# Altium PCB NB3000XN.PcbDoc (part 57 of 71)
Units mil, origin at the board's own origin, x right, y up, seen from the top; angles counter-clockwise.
Board outline 9527.56 x 6929.77 mil, 6 copper layers (Top Layer, GND+SHIELD, MidLayer1, MidLayer2, P2 - 3V3+5V0, Bottom Layer), stack 62.375 mil thick; 832 components, 1027 nets, 4655 pads, 4981 vias.
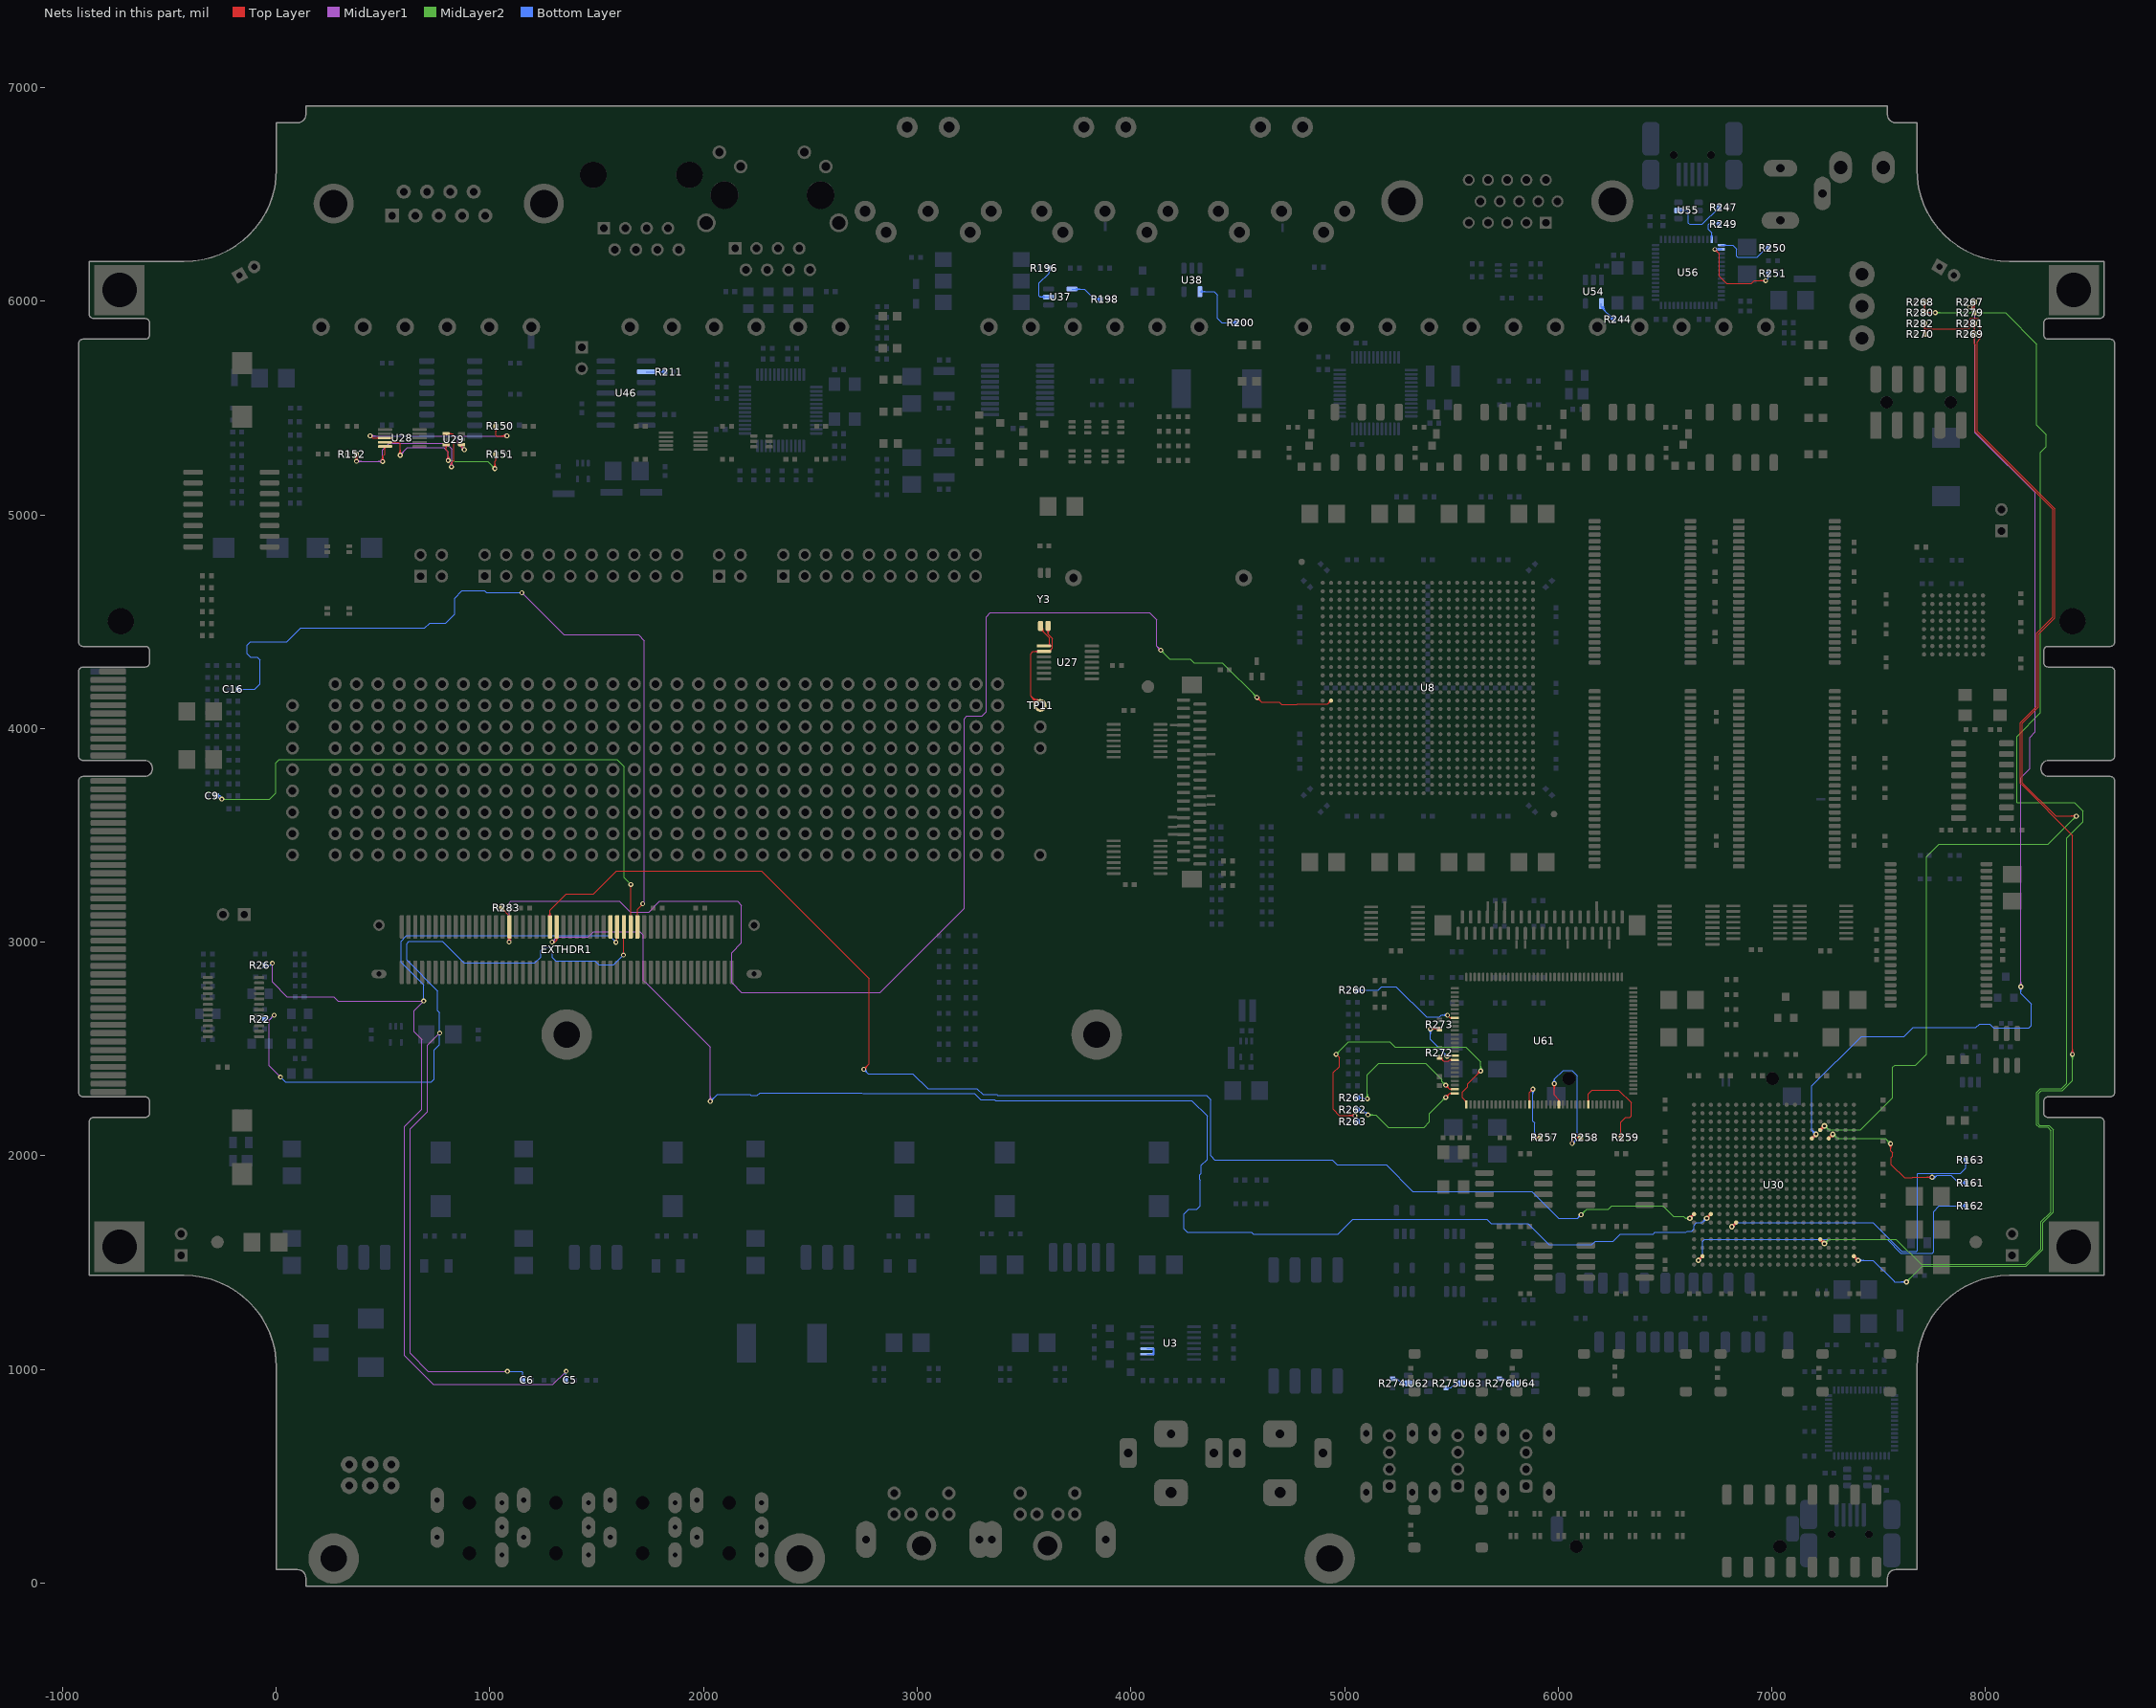
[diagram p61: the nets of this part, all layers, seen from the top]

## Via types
v1: diameter 23, hole 11.81, Top Layer to Bottom Layer, 3672 vias
v2: diameter 26, hole 11.81, Top Layer to Bottom Layer, 461 vias
v3: diameter 19, hole 11.81, Top Layer to Bottom Layer, tented both sides, 396 vias
v4: diameter 23.62, hole 11.81, Top Layer to Bottom Layer, 288 vias
v5: diameter 20, hole 11.81, Top Layer to Bottom Layer, 91 vias
v6: diameter 23, hole 11.81, Top Layer to Bottom Layer, tented both sides, 50 vias
v7: diameter 31, hole 11.81, Top Layer to Bottom Layer, 15 vias
v8: diameter 27.56, hole 11.81, Top Layer to Bottom Layer, tented both sides, 4 vias
v9: diameter 29, hole 11.81, Top Layer to Bottom Layer, 3 vias
v10: diameter 21, hole 11.81, Top Layer to Bottom Layer, 1 vias

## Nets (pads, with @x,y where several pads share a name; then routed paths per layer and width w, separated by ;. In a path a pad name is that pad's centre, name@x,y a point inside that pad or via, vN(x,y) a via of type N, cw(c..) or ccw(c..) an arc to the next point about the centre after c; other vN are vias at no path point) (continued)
NetR150_2: R150.2 U28.3 U29.4 | length 1239.4
  Top Layer w4: v4(440,5370) 450,5360 U28.3@509.29,5360 ; U28.3@479,5357.17 ccw(c472.17,5350.34) 472.17,5360 ccw(c472.17,5369.66) U28.3@479,5362.83 ; U29.4@864.34,5324.1 cw(c859.21,5317.17) 867.83,5317.17 ; U29.4@867.83,5328.82 867.83,5317.17 ; U29.4@871.33,5324.1 ccw(c876.46,5317.17) 867.83,5317.17 ; v4(880,5305) 867.83,5317.17 ; R150.2@1021.05,5407.92 cw(c1005.14,5392.01) 1027.64,5392.01 cw(c1050.14,5392.01) R150.2@1034.23,5407.92 ; R150.2@1023.88,5410.75 cw(c1014.8,5401.67) 1027.64,5401.67 cw(c1040.48,5401.67) R150.2@1031.4,5410.75 ; R150.2@1027.64,5415 1027.64,5372.36 1030,5370 v4(1080,5370) ; v4@1073.06,5363.06 ccw(c1056.31,5346.31) 1056.31,5370 ccw(c1056.31,5393.69) v4@1073.06,5376.94 ; v4@1075.89,5365.89 ccw(c1065.97,5355.97) 1065.97,5370 ccw(c1065.97,5384.03) v4@1075.89,5374.11
  MidLayer1 w4: v4(440,5370) 850,5370 ; v4@444.11,5365.89 cw(c454.03,5355.97) 454.03,5370 cw(c454.03,5384.03) v4@444.11,5374.11 ; v4@446.94,5363.06 cw(c463.69,5346.31) 463.69,5370 cw(c463.69,5393.69) v4@446.94,5376.94 ; v4@870.19,5305 ccw(c846.5,5305) 863.25,5321.75 ccw(c880,5338.5) v4@880,5314.81 ; v4@874.19,5305 ccw(c860.16,5305) 870.08,5314.92 ccw(c880,5324.84) v4@880,5310.81 ; v4(880,5305) 850,5335 850,5370 ; v4@1073.06,5363.06 ccw(c1056.31,5346.31) 1056.31,5370 ccw(c1056.31,5393.69) v4@1073.06,5376.94 ; v4@1075.89,5365.89 ccw(c1065.97,5355.97) 1065.97,5370 ccw(c1065.97,5384.03) v4@1075.89,5374.11 ; v4(1080,5370) 850,5370
NetR151_2: R151.2 U28.4 U29.3 | length 1293.9
  Top Layer w4: U28.4@509.29,5340.31 574.69,5340.31 580,5335 v4(580,5280) ; U28.4@539.58,5337.49 cw(c546.41,5330.66) 546.41,5340.31 cw(c546.41,5349.97) U28.4@539.58,5343.14 ; v4@573.06,5286.94 ccw(c556.31,5303.69) 580,5303.69 ccw(c603.69,5303.69) v4@586.94,5286.94 ; v4@575.89,5284.11 ccw(c565.97,5294.03) 580,5294.03 ccw(c594.03,5294.03) v4@584.11,5284.11 ; U29.3@790.85,5324.67 cw(c780.82,5314.64) 795,5314.64 cw(c809.18,5314.64) U29.3@799.15,5324.67 ; U29.3@795,5328.82 795,5305 805,5295 v1(805,5255) ; v1@798.28,5261.72 ccw(c782.06,5277.93) 805,5277.93 ccw(c827.93,5277.93) v1@811.72,5261.72 ; v1@801.11,5258.89 ccw(c791.72,5268.28) 805,5268.28 ccw(c818.28,5268.28) v1@808.89,5258.89 ; v1@1016.81,5223.43 ccw(c1000.59,5239.64) 1023.52,5239.64 ccw(c1046.46,5239.64) v1@1030.24,5223.43 ; v1@1019.64,5220.6 ccw(c1010.25,5229.99) 1023.52,5229.99 ccw(c1036.8,5229.99) v1@1027.41,5220.6 ; R151.2@1021.05,5277.92 cw(c1005.14,5262.01) 1027.64,5262.01 cw(c1050.13,5262.01) R151.2@1034.23,5277.92 ; v1(1023.52,5216.71) 1023.52,5250.89 1027.64,5255 R151.2@1027.64,5285 ; R151.2@1023.88,5280.75 cw(c1014.8,5271.67) 1027.64,5271.67 cw(c1040.48,5271.67) R151.2@1031.4,5280.75
  MidLayer1 w4: v4(580,5280) 615,5315 785,5315 805,5295 v1(805,5255) ; v4@580,5285.81 ccw(c580,5299.84) 589.92,5289.92 ccw(c599.84,5280) v4@585.81,5280 ; v4@580,5289.81 ccw(c580,5313.5) 596.75,5296.75 ccw(c613.5,5280) v4@589.81,5280 ; v1@798.28,5261.72 ccw(c782.06,5277.93) 805,5277.93 ccw(c827.93,5277.93) v1@811.72,5261.72 ; v1@801.11,5258.89 ccw(c791.72,5268.28) 805,5268.28 ccw(c818.28,5268.28) v1@808.89,5258.89
  MidLayer2 w4: v1(805,5255) 830,5255 835,5250 990.23,5250 v1(1023.52,5216.71) ; v1@808.89,5251.11 cw(c818.28,5241.72) 818.28,5255 cw(c818.28,5268.28) v1@808.89,5258.89 ; v1@811.72,5248.28 cw(c827.93,5232.06) 827.93,5255 cw(c827.93,5277.93) v1@811.72,5261.72 ; v1@1014.02,5216.71 ccw(c991.09,5216.71) 1007.31,5232.93 ccw(c1023.52,5249.14) v1@1023.52,5226.21 ; v1@1018.02,5216.71 ccw(c1004.75,5216.71) 1014.14,5226.1 ccw(c1023.52,5235.49) v1@1023.52,5222.21
NetR152_2: R152.2 U28.5 U29.1 | length 1361.7
  Top Layer w4: v1@368.65,5257.59 ccw(c352.43,5273.81) 375.37,5273.81 ccw(c398.3,5273.81) v1@382.08,5257.59 ; R152.2@369.59,5277.92 cw(c355.65,5263.97) 375.37,5263.97 ; v1@371.48,5254.76 ccw(c362.09,5264.15) 375.37,5264.15 ccw(c388.65,5264.15) v1@379.26,5254.76 ; v1(375.37,5250.87) 375.37,5284.19 R152.2@376.18,5285 ; v1@375.37,5260.05 cw(c400.64,5260.05) R152.2@382.77,5277.92 ; 375.37,5269.7 cw(c390.99,5269.7) R152.2@379.94,5280.75 ; v1@491.47,5256.76 ccw(c475.26,5272.98) 498.19,5272.98 ccw(c521.13,5272.98) v1@504.91,5256.76 ; v1@494.3,5253.93 ccw(c484.91,5263.32) 498.19,5263.32 ccw(c511.47,5263.32) v1@502.08,5253.93 ; v1(498.19,5250.04) 498.19,5273.9 509.29,5285 U28.5@509.29,5320.63 ; U28.5@506.46,5317.8 cw(c499.63,5310.97) 509.29,5310.97 cw(c518.95,5310.97) U28.5@512.12,5317.8 ; U29.1@795,5380 823.86,5380 831.86,5372 831.86,5255 820,5243.14 ; U29.1@808.01,5375.85 cw(c818.04,5365.82) 818.04,5380 cw(c818.04,5394.18) U29.1@808.01,5384.15 ; v4@814.63,5233.21 ccw(c808.13,5243.14) 820,5243.14 ; v4(820,5225) 820,5243.14 ; v4@825.37,5233.21 cw(c831.87,5243.14) 820,5243.14
  MidLayer1 w4: v1@373.52,5252.72 v1(375.37,5250.87) 444.11,5250.87 445.44,5249.54 498.19,5249.54 v1(498.19,5250.04) 498.19,5303.19 530,5335 795,5335 822.5,5307.5 822.5,5227.5 v4(820,5225) ; v1@379.26,5246.99 cw(c388.65,5237.6) 388.65,5250.87 cw(c388.65,5264.15) v1@379.26,5254.76 ; v1@382.08,5244.16 cw(c398.3,5227.94) 398.3,5250.87 cw(c398.3,5273.81) v1@382.08,5257.59 ; 474.05,5249.54 ccw(c474.05,5274.18) 491.47,5256.76 ccw(c475.26,5272.98) 498.19,5272.98 ccw(c521.13,5272.98) v1@504.91,5256.76 ; 476.46,5249.54 cw(c476.46,5228.31) v1@491.47,5243.32 ; 483.7,5249.54 ccw(c483.7,5264.53) 494.3,5253.93 ccw(c484.91,5263.32) 498.19,5263.32 ccw(c511.47,5263.32) v1@502.08,5253.93 ; 486.12,5249.54 cw(c486.12,5237.97) v1@494.3,5246.15 ; v4@813.06,5231.94 ccw(c790.28,5254.72) 822.5,5254.72 ; v4@815.89,5229.11 ccw(c799.94,5245.06) 822.5,5245.06 ; 822.5,5242.65 ccw(c837.65,5242.65) v4@826.94,5231.94
NetR161_2: R161.2 U30.D5 | length 1265.7
  Top Layer w4: v1@7548.81,2050.32 cw(c7532.59,2034.11) 7555.52,2034.11 cw(c7578.46,2034.11) v1@7562.24,2050.32 ; v1@7551.64,2053.15 cw(c7542.25,2043.76) 7555.52,2043.76 cw(c7568.8,2043.76) v1@7559.41,2053.15 ; v1(7555.52,2057.04) 7555.52,2023.76 7565.51,2013.78 7565.51,1999.02 7559.5,1993.02 7559.5,1959.44 7621.7,1897.24 7657.24,1897.24 7660,1900 v1(7750,1900) ; v1@7743.28,1893.28 ccw(c7727.06,1877.06) 7727.06,1900 ccw(c7727.06,1922.93) v1@7743.28,1906.72 ; v1@7746.11,1896.11 ccw(c7736.72,1886.72) 7736.72,1900 ccw(c7736.72,1913.28) v1@7746.11,1903.89
  Top Layer w8: U30.D5@7265.91,2081.54 v2(7285.59,2101.22) ; U30.D5@7265.91,2087.38 ccw(c7265.91,2101.48) 7275.88,2091.51 ccw(c7285.85,2081.54) U30.D5@7271.75,2081.54 ; v2@7276.59,2101.22 cw(c7254.86,2101.22) 7270.23,2085.86 cw(c7285.59,2070.49) v2@7285.59,2092.22
  MidLayer2 w4: v2@7285.59,2090.22 cw(c7285.59,2063.66) 7304.37,2082.44 cw(c7323.15,2101.22) v2@7296.59,2101.22 ; v2@7285.59,2094.22 cw(c7285.59,2077.32) 7297.54,2089.27 cw(c7309.49,2101.22) v2@7292.59,2101.22 ; v2(7285.59,2101.22) 7304.77,2082.04 7530.52,2082.04 v1(7555.52,2057.04) ; v1@7546.02,2057.04 ccw(c7523.09,2057.04) 7539.31,2073.26 ccw(c7555.52,2089.48) v1@7555.52,2066.54 ; v1@7550.02,2057.04 ccw(c7536.75,2057.04) 7546.14,2066.43 ccw(c7555.52,2075.82) v1@7555.52,2062.54
  Bottom Layer w4: v1@7745.93,1894.93 ccw(c7752.96,1903.69) 7760.9,1895.75 ; v1@7748.44,1898.05 ccw(c7755.77,1907.19) 7764.05,1898.91 ; v1@7750,1891.71 7756.86,1891.71 7757.57,1892.43 7773.52,1908.37 ; v1@7750,1892.18 v1(7750,1900) ; v1@7750.94,1901.17 ccw(c7758.58,1910.7) 7767.21,1902.06 ; v1@7753.44,1904.29 ccw(c7761.39,1914.2) 7770.37,1905.22 ; v1@7755.94,1907.41 ccw(c7764.2,1917.7) 7773.52,1908.37 ; R161.2@7902.23,1866.74 ccw(c7886.32,1850.84) 7886.32,1873.33 ccw(c7886.32,1895.83) R161.2@7902.23,1879.92 ; R161.2@7905.06,1869.57 ccw(c7895.98,1860.49) 7895.98,1873.33 ccw(c7895.98,1886.18) R161.2@7905.06,1877.09 ; R161.2@7908.82,1873.33 7873.52,1873.33 7838.48,1908.37 7773.52,1908.37
NetR162_2: R162.2 U30.W19 | length 1818.5
  Top Layer w8: v2(6655.67,1510.67) U30.W19@6675.35,1530.35 ; v2@6655.67,1519.67 ccw(c6655.67,1541.4) 6671.03,1526.03 ccw(c6686.4,1510.67) v2@6664.67,1510.67 ; U30.W19@6669.51,1530.35 cw(c6655.41,1530.35) 6665.38,1520.38 cw(c6675.35,1510.41) U30.W19@6675.35,1524.51
  Bottom Layer w4: v2(6655.67,1510.67) 6675.86,1530.86 6675.86,1600.04 6684.86,1609.04 7540,1609.04 7604.04,1545 7750,1545 7756.86,1551.86 7756.86,1640 ; v2@6655.67,1517.67 ccw(c6655.67,1534.57) 6667.62,1522.62 ccw(c6679.57,1510.67) v2@6662.67,1510.67 ; v2@6655.67,1521.67 ccw(c6655.67,1548.23) 6674.45,1529.45 ccw(c6693.23,1510.67) v2@6666.67,1510.67 ; 7756.86,1591.71 7756.86,1640 ; R162.2@7902.23,1758.41 ccw(c7886.32,1742.5) 7886.32,1765 ccw(c7886.32,1787.5) R162.2@7902.23,1771.59 ; R162.2@7905.06,1761.24 ccw(c7895.98,1752.16) 7895.98,1765 ccw(c7895.98,1777.84) R162.2@7905.06,1768.76 ; R162.2@7908.82,1765 7781.86,1765 7756.86,1740 7756.86,1640
NetR163_2: R163.2 U30.R15 | length 1799.5
  Top Layer w8: v2(6813.15,1668.15) U30.R15@6832.83,1687.83 ; v2@6813.15,1677.15 ccw(c6813.15,1698.88) 6828.51,1683.51 ccw(c6843.88,1668.15) v2@6822.15,1668.15 ; U30.R15@6826.99,1687.83 cw(c6812.89,1687.83) 6822.86,1677.86 cw(c6832.83,1667.89) U30.R15@6832.83,1681.99
  Bottom Layer w4: v2(6813.15,1668.15) 6832.71,1687.71 7472.65,1687.71 7607.35,1553 7678,1553 7681.86,1556.86 7681.86,1610 ; v2@6813.15,1675.15 ccw(c6813.15,1692.05) 6825.1,1680.1 ; v2@6813.15,1679.15 ccw(c6813.15,1705.71) 6831.93,1686.93 ccw(c6850.7,1668.15) v2@6824.15,1668.15 ; v2@6820.15,1668.15 cw(c6837.05,1668.15) 6825.1,1680.1 ; 7681.86,1588.71 7681.86,1610 ; R163.2@7902.23,1974.59 cw(c7886.32,1958.68) 7908.82,1958.68 cw(c7931.32,1958.68) R163.2@7915.41,1974.59 ; R163.2@7905.06,1977.41 cw(c7895.98,1968.33) 7908.82,1968.33 cw(c7921.66,1968.33) R163.2@7912.58,1977.41 ; R163.2@7908.82,1981.67 7908.82,1943.37 7883.44,1918 7683.15,1918 7681.86,1916.71 7681.86,1610
NetR196_1: R196.1 U37.2 | length 310.8
  Bottom Layer w4: U37.2@3594.16,6013.06 ccw(c3577.42,5996.31) 3577.42,6020 ccw(c3577.42,6043.69) U37.2@3594.16,6026.94 ; U37.2@3596.99,6015.89 ccw(c3587.07,6005.97) 3587.07,6020 ccw(c3587.07,6034.03) U37.2@3596.99,6024.11 ; R196.1@3609.59,6147.92 cw(c3593.68,6132.01) 3616.18,6132.01 cw(c3638.68,6132.01) R196.1@3622.77,6147.92 ; R196.1@3612.42,6150.75 cw(c3603.34,6141.67) 3616.18,6141.67 cw(c3629.02,6141.67) R196.1@3619.94,6150.75 ; U37.2@3614.88,6020 3575,6020 3570,6025 3570,6085 3616.18,6131.18 R196.1@3616.18,6155
NetR198_1: R198.1 U37.4 | length 268.1
  Bottom Layer w4: U37.4@3725.12,6057.4 3782.83,6057.4 3830.23,6010 R198.1@3858.82,6010 ; U37.4@3743.01,6053.29 cw(c3752.93,6043.37) 3752.93,6057.4 cw(c3752.93,6071.43) U37.4@3743.01,6061.51 ; U37.4@3745.84,6050.46 cw(c3762.58,6033.72) 3762.58,6057.4 cw(c3762.58,6081.09) U37.4@3745.84,6064.34 ; R198.1@3852.23,6003.41 ccw(c3836.32,5987.5) 3836.32,6010 ccw(c3836.32,6032.5) R198.1@3852.23,6016.59 ; R198.1@3855.06,6006.24 ccw(c3845.98,5997.16) 3845.98,6010 ccw(c3845.98,6022.84) R198.1@3855.06,6013.76
NetR200_1: R200.1 U38.4 | length 409.7
  Bottom Layer w4: U38.4@4323.24,6044.88 4390,6044.88 4405,6029.88 4405,5920 4425,5900 R200.1@4493.82,5900 ; U38.4@4327.35,6040.77 cw(c4337.27,6030.85) 4337.27,6044.88 cw(c4337.27,6058.91) U38.4@4327.35,6048.99 ; U38.4@4330.18,6037.94 cw(c4346.93,6021.2) 4346.93,6044.88 cw(c4346.93,6068.57) U38.4@4330.18,6051.82 ; R200.1@4487.23,5893.41 ccw(c4471.32,5877.5) 4471.32,5900 ccw(c4471.32,5922.5) R200.1@4487.23,5906.59 ; R200.1@4490.06,5896.24 ccw(c4480.98,5887.16) 4480.98,5900 ccw(c4480.98,5912.84) R200.1@4490.06,5903.76
NetR211_2: R211.2 U46.2 | length 164.7
  Bottom Layer w4: U46.2@1731.54,5670.08 1780.52,5670.08 ; U46.2@1771.41,5664.96 cw(c1780.52,5659.4) 1780.52,5670.08 ; U46.2@1771.41,5675.19 ccw(c1780.52,5680.75) 1780.52,5670.08 ; R211.2@1812.23,5663.41 ccw(c1796.32,5647.5) 1796.32,5670 ccw(c1796.32,5692.5) R211.2@1812.23,5676.59 ; R211.2@1815.06,5666.24 ccw(c1805.98,5657.16) 1805.98,5670 ccw(c1805.98,5682.84) R211.2@1815.06,5673.76 ; R211.2@1818.82,5670 1780.6,5670 1780.52,5670.08
NetR244_2: R244.2 U54.4 | length 223.2
  Bottom Layer w4: U54.4@6202.4,5966.29 cw(c6202.4,5953.92) 6211.15,5962.67 ; U54.4@6202.4,5989.88 6202.4,5971.42 R244.2@6258.82,5915 ; U54.4@6204.21,5976.1 ccw(c6219.9,5976.1) U54.4@6208.81,5965.01 ; U54.4@6208.21,5976.1 ccw(c6233.55,5976.1) 6215.63,5958.18 ; U54.4@6212.21,5976.1 ccw(c6247.21,5976.1) 6222.46,5951.36 ; 6242.07,5931.75 ccw(c6258.82,5948.5) R244.2@6258.82,5924.81 ; 6243.26,5930.56 cw(c6228.19,5915.49) R244.2@6249.5,5915.49 ; R244.2@6248.9,5924.92 ccw(c6258.82,5934.84) R244.2@6258.82,5920.81 ; R244.2@6250.09,5923.73 cw(c6241.85,5915.49) R244.2@6253.5,5915.49
NetR247_2: R247.2 U55.5 | length 413
  Bottom Layer w4: U55.5@6562.76,6425 6605,6425 6610,6420 6610,6365 6615,6360 6673.82,6360 R247.2@6753.82,6440 ; U55.5@6574.16,6419.5 cw(c6587.44,6406.22) 6587.44,6425 cw(c6587.44,6443.78) U55.5@6574.16,6430.5 ; U55.5@6576.99,6416.67 cw(c6597.1,6396.56) 6597.1,6425 cw(c6597.1,6453.44) U55.5@6576.99,6433.33 ; 6737.07,6423.25 cw(c6753.82,6406.5) R247.2@6753.82,6430.19 ; 6738.26,6424.44 ccw(c6723.19,6439.51) R247.2@6744.5,6439.51 ; R247.2@6743.9,6430.08 cw(c6753.82,6420.16) R247.2@6753.82,6434.19 ; R247.2@6745.09,6431.27 ccw(c6736.85,6439.51) R247.2@6748.5,6439.51
NetR249_2: R249.2 U56.13 | length 150.1
  Bottom Layer w4: U56.13@6715.44,6303.09 ccw(c6708.61,6309.92) 6718.27,6309.92 ccw(c6727.92,6309.92) U56.13@6721.1,6303.09 ; U56.13@6718.27,6289.33 6718.27,6320.66 6703.48,6335.44 6703.48,6358.16 6715.98,6370.66 6731.75,6370.66 6742.41,6360 R249.2@6753.82,6360
NetR250_2: R250.2 U56.15 | length 294.6
  Bottom Layer w4: U56.15@6764.33,6262.95 6817.05,6262.95 6835.69,6244.31 6835.69,6219.52 6835.69,6211.14 6839.21,6207.62 6900,6207.62 6930.79,6207.62 6973.17,6250 R250.2@6983.82,6250 ; U56.15@6778.09,6260.12 cw(c6784.92,6253.3) 6784.92,6262.95 cw(c6784.92,6272.61) U56.15@6778.09,6265.78
NetR251_2: R251.2 U56.16 | length 603.5
  Top Layer w4: v5@6733,6235.27 cw(c6733,6215.95) 6746.66,6229.61 cw(c6760.31,6243.27) v5@6741,6243.27 ; v5(6733,6243.27) 6755,6221.27 6755,6116.23 6775.37,6095.86 ; 6773.52,6097.71 6775.37,6095.86 ; v1@6964.47,6089.32 ccw(c6948.26,6073.11) 6948.26,6096.04 ccw(c6948.26,6118.98) v1@6964.47,6102.76 ; v1@6967.3,6092.15 ccw(c6957.91,6082.76) 6957.91,6096.04 ccw(c6957.91,6109.32) v1@6967.3,6099.93 ; v1(6971.19,6096.04) 6917.67,6096.04 6905,6083.37 6787.86,6083.37 6775.37,6095.86
  Bottom Layer w4: v1(6971.19,6096.04) 6983.82,6108.67 ; R251.2@6977.61,6122.56 cw(c6965.18,6108.67) 6983.82,6108.67 ; R251.2@6980.27,6125.54 cw(c6973.18,6117.61) 6983.82,6117.61 cw(c6994.46,6117.62) R251.2@6987.36,6125.54 ; R251.2@6983.82,6130 6983.82,6108.67 ; R251.2@6990.03,6122.56 ccw(c7002.46,6108.67) 6983.82,6108.67
  Bottom Layer w8: v5(6733,6243.27) U56.16@6764.33,6243.27 ; v5@6737.24,6239.03 cw(c6747.48,6228.78) 6747.48,6243.27 cw(c6747.48,6257.75) v5@6737.24,6247.51
NetR257_1: R257.1 U61.16 | length 634.5
  Top Layer w4: U61.16@5862.45,2256.02 ccw(c5855.62,2262.85) 5865.28,2262.85 ccw(c5874.93,2262.85) U61.16@5868.1,2256.02 ; U61.16@5865.27,2240 5865.27,2295.79 v1(5881.86,2312.37) ; v1@5872.36,2312.37 cw(c5849.42,2312.37) 5865.64,2296.16 cw(c5881.86,2279.94) v1@5881.86,2302.87 ; v1@5876.36,2312.37 cw(c5863.08,2312.37) 5872.47,2302.99 cw(c5881.86,2293.6) v1@5881.86,2306.87 ; v1(5890,2085) R257.1@5916.33,2085 ; v1@5893.89,2081.11 cw(c5903.28,2071.72) 5903.28,2085 cw(c5903.28,2098.28) v1@5893.89,2088.89 ; v1@5896.72,2078.28 cw(c5912.93,2062.06) 5912.93,2085 cw(c5912.93,2107.93) v1@5896.72,2091.72 ; R257.1@5909.74,2078.41 ccw(c5893.83,2062.5) 5893.83,2085 ccw(c5893.83,2107.5) R257.1@5909.74,2091.59 ; R257.1@5912.57,2081.24 ccw(c5903.49,2072.16) 5903.49,2085 ccw(c5903.49,2097.84) R257.1@5912.57,2088.76
  Bottom Layer w4: v1@5875.14,2305.66 cw(c5858.92,2289.44) 5881.86,2289.44 cw(c5904.79,2289.44) v1@5888.57,2305.66 ; v1@5877.97,2308.49 cw(c5868.58,2299.1) 5881.86,2299.1 cw(c5895.14,2299.1) v1@5885.75,2308.49 ; v1(5881.86,2312.37) 5881.86,2163.14 5890,2155 v1(5890,2085) ; v1@5883.28,2091.72 ccw(c5867.06,2107.93) 5890,2107.93 ccw(c5912.93,2107.93) v1@5896.72,2091.72 ; v1@5886.11,2088.89 ccw(c5876.72,2098.28) 5890,2098.28 ccw(c5903.28,2098.28) v1@5893.89,2088.89
NetR258_1: R258.1 U61.23 | length 934.1
  Top Layer w4: v1@5975.14,2330.99 cw(c5958.92,2314.77) 5981.86,2314.77 cw(c6004.79,2314.77) v1@5988.57,2330.99 ; v1@5977.97,2333.82 cw(c5968.58,2324.43) 5981.86,2324.43 cw(c5995.14,2324.43) v1@5985.75,2333.82 ; v1(5981.86,2337.71) 5981.86,2285.04 6003.07,2263.83 U61.23@6003.07,2240 ; U61.23@6000.24,2256.02 ccw(c5993.41,2262.85) 6003.07,2262.85 ; 6003.07,2262.85 ccw(c6012.73,2262.85) U61.23@6005.9,2256.02 ; v1@6059.01,2065.59 ccw(c6047.46,2079.04) 6065.19,2079.04 ; v1@6061.61,2062.55 ccw(c6054.93,2070.34) 6065.19,2070.34 ccw(c6075.45,2070.34) v1@6068.77,2062.55 ; v1(6065.19,2058.37) 6065.19,2079.04 ; v1@6071.38,2065.59 cw(c6082.92,2079.04) 6065.19,2079.04 ; R258.1@6098.48,2078.41 ccw(c6082.58,2062.5) 6082.58,2085 ccw(c6082.58,2107.5) R258.1@6098.48,2091.59 ; R258.1@6101.31,2081.24 ccw(c6092.23,2072.16) 6092.23,2085 ccw(c6092.23,2097.84) R258.1@6101.31,2088.76 ; R258.1@6105.07,2085 6071.15,2085 6065.19,2079.04
  Bottom Layer w4: v1@5975.67,2344.92 ccw(c5964.13,2358.37) 5981.86,2358.37 ; v1@5978.28,2341.88 ccw(c5971.59,2349.67) 5981.86,2349.67 ccw(c5992.12,2349.67) v1@5985.44,2341.88 ; v1(5981.86,2337.71) 5981.86,2358.37 ; v1@5988.04,2344.92 cw(c5999.58,2358.37) 5981.86,2358.37 ; v1(6065.19,2058.37) 6090.19,2083.37 6090.19,2375.04 6065.19,2400.04 6023.52,2400.04 5981.86,2358.37 ; v1@6065.19,2063.87 ccw(c6065.19,2077.15) 6074.58,2067.76 ccw(c6083.97,2058.37) v1@6070.69,2058.37 ; v1@6065.19,2067.87 ccw(c6065.19,2090.81) 6081.41,2074.59 ccw(c6097.63,2058.37) v1@6074.69,2058.37
NetR259_1: R259.1 U61.30 | length 550.8
  Top Layer w4: U61.30@6138.04,2256.02 ccw(c6131.21,2262.85) 6140.87,2262.85 ; U61.30@6140.86,2240 6140.87,2290.87 6158.71,2308.71 6282.86,2308.71 6342.01,2249.55 6342.01,2187.01 6335,2180 6315,2180 6293.82,2158.82 R259.1@6293.82,2085 ; 6140.87,2262.85 ccw(c6150.52,2262.85) U61.30@6143.69,2256.02 ; R259.1@6287.23,2092.08 ccw(c6271.32,2107.99) 6293.82,2107.99 ccw(c6316.32,2107.99) R259.1@6300.41,2092.08 ; R259.1@6290.06,2089.25 ccw(c6280.98,2098.33) 6293.82,2098.33 ccw(c6306.66,2098.33) R259.1@6297.58,2089.25
NetR260_1: R260.1 U61.110 | length 657.3
  Top Layer w4: v1(5481.86,2658.37) 5493.93,2646.31 U61.110@5516.83,2646.31 ; U61.110@5500.81,2643.48 ccw(c5493.98,2636.65) 5493.98,2646.31 ccw(c5493.98,2655.96) U61.110@5500.81,2649.13
  Bottom Layer w4: R260.1@5061.18,2775 5156.81,2775 5173.52,2791.71 5241.54,2791.71 5383.21,2650.04 5445,2650.04 5453.33,2658.37 v1(5481.86,2658.37) ; R260.1@5064.94,2771.24 cw(c5074.02,2762.16) 5074.02,2775 cw(c5074.02,2787.84) R260.1@5064.94,2778.76 ; R260.1@5067.77,2768.41 cw(c5083.68,2752.5) 5083.68,2775 cw(c5083.68,2797.5) R260.1@5067.77,2781.59 ; v1@5475.14,2651.66 ccw(c5458.92,2635.44) 5458.92,2658.37 ccw(c5458.92,2681.31) v1@5475.14,2665.09 ; v1@5477.97,2654.49 ccw(c5468.58,2645.1) 5468.58,2658.37 ccw(c5468.58,2671.65) v1@5477.97,2662.26
NetR261_1: R261.1 U61.127 | length 889.7
  Top Layer w4: v1@5473.52,2321.21 cw(c5473.52,2298.27) 5489.74,2314.49 cw(c5505.96,2330.71) v1@5483.02,2330.71 ; v1@5473.52,2325.21 cw(c5473.52,2311.93) 5482.91,2321.32 cw(c5492.3,2330.71) v1@5479.02,2330.71 ; v1(5473.52,2330.71) 5492.57,2311.66 U61.127@5516.83,2311.66 ; U61.127@5500.81,2308.83 ccw(c5493.98,2302) 5493.98,2311.66 ccw(c5493.98,2321.32) U61.127@5500.81,2314.49
  MidLayer2 w4: v1@5100.14,2273.43 ccw(c5083.92,2289.64) 5106.86,2289.64 ccw(c5129.79,2289.64) v1@5113.57,2273.43 ; v1@5102.97,2270.6 ccw(c5093.58,2279.99) 5106.86,2279.99 ccw(c5120.14,2279.99) v1@5110.75,2270.6 ; v1(5106.86,2266.71) 5106.86,2379.23 5161,2433.37 5210,2433.37 5379.86,2433.37 5456.52,2356.71 5456.52,2347.71 v1(5473.52,2330.71) ; v1@5464.02,2330.71 ccw(c5441.09,2330.71) 5457.31,2346.93 ccw(c5473.52,2363.14) v1@5473.52,2340.21 ; v1@5468.02,2330.71 ccw(c5454.75,2330.71) 5464.14,2340.1 ccw(c5473.52,2349.49) v1@5473.52,2336.21
  Bottom Layer w4: R261.1@5061.18,2271.82 5087.08,2271.82 5092.19,2266.71 v1(5106.86,2266.71) ; R261.1@5064.94,2268.06 cw(c5074.02,2258.98) 5074.02,2271.82 cw(c5074.02,2284.66) R261.1@5064.94,2275.58 ; R261.1@5067.77,2265.23 cw(c5083.68,2249.32) 5083.68,2271.82 cw(c5083.68,2294.32) R261.1@5067.77,2278.41
NetR262_1: R262.1 U61.128 | length 876.5
  Top Layer w4: v1(5473.52,2273.71) 5491.79,2291.98 U61.128@5516.83,2291.98 ; v1@5473.52,2279.21 ccw(c5473.52,2292.49) 5482.91,2283.1 ccw(c5492.3,2273.71) v1@5479.02,2273.71 ; v1@5473.52,2283.21 ccw(c5473.52,2306.14) 5489.74,2289.93 ccw(c5505.96,2273.71) v1@5483.02,2273.71 ; U61.128@5500.81,2289.15 ccw(c5493.98,2282.32) 5493.98,2291.98 ccw(c5493.98,2301.63) U61.128@5500.81,2294.8
  MidLayer2 w4: v1(5109.52,2191.71) 5146.86,2191.71 5205.19,2133.37 5371.9,2133.37 5398.52,2160 5398.52,2198.71 v1(5473.52,2273.71) ; v1@5113.41,2187.82 cw(c5122.8,2178.43) 5122.8,2191.71 cw(c5122.8,2204.99) v1@5113.41,2195.6 ; v1@5116.24,2184.99 cw(c5132.46,2168.77) 5132.46,2191.71 cw(c5132.46,2214.64) v1@5116.24,2198.43 ; v1@5464.02,2273.71 cw(c5441.09,2273.71) 5457.31,2257.49 cw(c5473.52,2241.27) v1@5473.52,2264.21 ; v1@5468.02,2273.71 cw(c5454.75,2273.71) 5464.14,2264.32 cw(c5473.52,2254.93) v1@5473.52,2268.21
  Bottom Layer w4: R262.1@5061.18,2215.91 5083.52,2215.91 ; R262.1@5064.96,2212.17 cw(c5073.93,2203.28) 5073.93,2215.91 cw(c5073.93,2228.54) R262.1@5064.96,2219.65 ; R262.1@5067.8,2209.35 cw(c5083.52,2193.79) 5083.52,2215.91 ; R262.1@5067.8,2222.47 ccw(c5083.52,2238.03) 5083.52,2215.91 ; v1@5100.02,2191.71 ccw(c5077.09,2191.71) 5093.31,2207.93 ccw(c5109.52,2224.14) v1@5109.52,2201.21 ; v1@5104.02,2191.71 ccw(c5090.75,2191.71) 5100.14,2201.1 ccw(c5109.52,2210.49) v1@5109.52,2197.21 ; v1(5109.52,2191.71) 5084.52,2216.71 5084.32,2216.71 5083.52,2215.91
NetR263_1: R263.1 U61.1 | length 1659.1
  Top Layer w4: v1(4960,2475) 4961.35,2475 4975.5,2460.85 4975.5,2418.43 4947.69,2390.62 4947.69,2217.31 4975,2190 5046.56,2190 v1(5048.52,2188.04) ; 5020.86,2190 cw(c5020.86,2160.38) v1@5041.81,2181.32 ; 5030.32,2190 ccw(c5030.32,2206.25) v1@5041.81,2194.76 ; 5030.52,2190 cw(c5030.52,2170.03) v1@5044.64,2184.15 ; 5562.03,2262.78 cw(c5552.44,2253.19) U61.1@5566,2253.19 ; U61.1@5565.93,2258.88 ccw(c5570,2262.94) U61.1@5570,2257.19 ; U61.1@5570,2240 5570,2254.81 5552.19,2272.62 5552.19,2299.16 5577.5,2324.47 5577.5,2337.35 v1(5637.52,2397.37) ; v1@5628.02,2397.37 cw(c5605.09,2397.37) 5621.31,2381.16 cw(c5637.52,2364.94) v1@5637.52,2387.87 ; v1@5632.02,2397.37 cw(c5618.75,2397.37) 5628.14,2387.99 cw(c5637.52,2378.6) v1@5637.52,2391.87
  MidLayer2 w4: v1(4960,2475) 5018.37,2533.37 5211.69,2533.37 5236.69,2508.37 5568.56,2508.37 5637.52,2439.41 v1(5637.52,2397.37) ; v1@4960,2480.5 ccw(c4960,2493.78) 4969.39,2484.39 ccw(c4978.78,2475) v1@4965.5,2475 ; v1@4960,2484.5 ccw(c4960,2507.43) 4976.22,2491.22 ccw(c4992.43,2475) v1@4969.5,2475 ; v1@5630.81,2404.09 ccw(c5614.59,2420.31) 5637.52,2420.31 ccw(c5660.46,2420.31) v1@5644.24,2404.09 ; v1@5633.64,2401.26 ccw(c5624.25,2410.65) 5637.52,2410.65 ccw(c5650.8,2410.65) v1@5641.41,2401.26
  Bottom Layer w4: v1(5048.52,2188.04) 5061.18,2175.38 ; R263.1@5057.11,2168.87 ccw(c5053.94,2175.38) 5061.18,2175.38 ; R263.1@5061.18,2160 5061.18,2175.38 ; R263.1@5065.26,2168.87 cw(c5068.42,2175.38) 5061.18,2175.38
NetR267_2: R267.2 R279.2 U30.F5 | length 5483.9
  Top Layer w4: v1(7927,5972) 7948,5972 ; v1@7931.13,5968.37 cw(c7939.16,5961.31) 7939.16,5972 cw(c7939.16,5982.69) v1@7931.13,5975.63 ; v1@7934.14,5965.73 cw(c7948,5953.54) 7948,5972 ; v1@7934.14,5978.27 ccw(c7948,5990.46) 7948,5972 ; R279.2@7941.58,5953.75 ccw(c7925.68,5969.66) 7948.17,5969.66 ccw(c7970.67,5969.66) R279.2@7954.76,5953.75 ; R267.2@7941.58,5989.92 cw(c7925.68,5974.01) 7948.17,5974.01 cw(c7970.67,5974.01) R267.2@7954.76,5989.92 ; R279.2@7944.41,5950.92 ccw(c7935.33,5960) 7948.17,5960 ccw(c7961.01,5960) R279.2@7951.93,5950.92 ; R267.2@7944.41,5992.75 cw(c7935.33,5983.67) 7948.17,5983.67 cw(c7961.01,5983.67) R267.2@7951.93,5992.75 ; R279.2@7948.17,5946.67 R267.2@7948.17,5997
  Top Layer w8: U30.F5@7187.17,2081.54 v2(7206.85,2101.22) ; U30.F5@7187.17,2087.38 ccw(c7187.17,2101.48) 7197.14,2091.51 ccw(c7207.11,2081.54) U30.F5@7193.01,2081.54 ; v2@7197.85,2101.22 cw(c7176.12,2101.22) 7191.49,2085.86 cw(c7206.85,2070.49) v2@7206.85,2092.22
  MidLayer1 w4: v1@7927,5962.5 cw(c7927,5939.56) 7943.22,5955.78 cw(c7959.44,5972) v1@7936.5,5972 ; v1@7927,5966.5 cw(c7927,5953.22) 7936.39,5962.61 cw(c7945.78,5972) v1@7932.5,5972 ; v1(7927,5972) 7950.81,5948.19 7950.81,5385.42 7979.95,5356.28 8232.52,5103.71 8232.52,3984.04 8207.19,3958.71 8207.19,3812.19 8165.19,3770.19 v1(8165.19,2791.71) ; v1@8158.47,2798.43 ccw(c8142.26,2814.64) 8165.19,2814.64 ccw(c8188.13,2814.64) v1@8171.91,2798.43 ; v1@8161.3,2795.6 ccw(c8151.91,2804.99) 8165.19,2804.99 ccw(c8178.47,2804.99) v1@8169.08,2795.6
  Bottom Layer w4: v2@7195.85,2101.22 ccw(c7169.3,2101.22) 7188.07,2120 ccw(c7206.85,2138.78) v2@7206.85,2112.22 ; v2@7199.85,2101.22 ccw(c7182.95,2101.22) 7194.9,2113.17 ccw(c7206.85,2125.12) v2@7206.85,2108.22 ; v2(7206.85,2101.22) 7187.52,2120.55 7187.52,2327.04 7418.86,2558.37 7618.86,2558.37 7660.52,2600.04 7955.52,2600.04 7972.19,2616.71 8020.86,2616.71 8037.86,2599.71 8203.54,2599.71 8215,2611.16 8215,2710.19 8165.19,2760 v1(8165.19,2791.71) ; v1@8158.47,2784.99 cw(c8142.26,2768.77) 8165.19,2768.77 cw(c8188.13,2768.77) v1@8171.91,2784.99 ; v1@8161.3,2787.82 cw(c8151.91,2778.43) 8165.19,2778.43 cw(c8178.47,2778.43) v1@8169.08,2787.82
NetR268_2: R268.2 R280.2 U30.E17 | length 6988.8
  Top Layer w4: R280.2@7709.59,5953.75 ccw(c7693.68,5969.66) 7716.18,5969.66 ccw(c7738.68,5969.66) 7722.77,5953.75 ccw(c7739.06,5970.04) 7739.06,5947 ; R268.2@7709.59,5989.92 cw(c7693.68,5974.01) 7716.18,5974.01 cw(c7738.68,5974.01) R268.2@7722.77,5989.92 ; R280.2@7712.42,5950.92 ccw(c7703.34,5960) 7716.18,5960 ccw(c7729.02,5960) 7719.94,5950.92 ccw(c7729.4,5960.38) 7729.4,5947 ; R268.2@7712.42,5992.75 cw(c7703.34,5983.67) 7716.18,5983.67 cw(c7729.02,5983.67) R268.2@7719.94,5992.75 ; R268.2@7716.18,5997 R280.2@7716.18,5947 ; R280.2@7719.94,5943.4 cw(c7728.64,5934.7) 7728.64,5947 ; R280.2@7721.14,5941.71 R280.2@7716.18,5946.67 R280.2@7716.18,5947 ; R280.2@7722.77,5940.57 cw(c7738.3,5925.04) 7738.3,5947 ; v1@7758.28,5940.28 ccw(c7742.06,5924.06) 7742.06,5947 ccw(c7742.06,5969.93) v1@7758.28,5953.72 ; v1@7761.11,5943.11 ccw(c7751.72,5933.72) 7751.72,5947 ccw(c7751.72,5960.28) v1@7761.11,5950.89 ; v1(7765,5947) R280.2@7716.18,5947
  Top Layer w8: U30.E17@7226.54,1603.25 cw(c7226.54,1589.15) 7236.51,1599.12 cw(c7246.48,1609.09) U30.E17@7232.38,1609.09 ; U30.E17@7226.54,1609.09 v2(7246.22,1589.41) ; v2@7237.22,1589.41 ccw(c7215.49,1589.41) 7230.86,1604.77 ccw(c7246.22,1620.14) v2@7246.22,1598.41
  MidLayer2 w4: v2(7246.22,1589.41) 7265.52,1608.71 7581.52,1608.71 7698.52,1491.71 8186.69,1491.71 8260,1565.02 8260,1690.88 8306.86,1737.73 8306.86,2118.14 8290,2135 8250.18,2135 8239.86,2145.32 8239.86,2296.73 8258.13,2315 8355,2315 8380,2340 8380,3486.87 8456.52,3563.39 8456.52,3613.48 8417,3653 8148.31,3653 8146.86,3654.46 8146.86,3963.81 8256.86,4073.81 8256.86,5291.86 8285,5320 8285,5375 8240,5420 8240,5800 8093,5947 v1(7765,5947) ; v2@7246.22,1596.41 ccw(c7246.22,1613.31) 7258.17,1601.36 ccw(c7270.12,1589.41) v2@7253.22,1589.41 ; v2@7246.22,1600.41 ccw(c7246.22,1626.97) 7265,1608.19 ; v2@7257.22,1589.41 cw(c7283.77,1589.41) 7265,1608.19 ; v1@7768.89,5943.11 cw(c7778.28,5933.72) 7778.28,5947 cw(c7778.28,5960.28) v1@7768.89,5950.89 ; v1@7771.72,5940.28 cw(c7787.94,5924.06) 7787.94,5947 cw(c7787.94,5969.93) v1@7771.72,5953.72
NetR269_2: R269.2 R281.2 U30.A19 | length 6369.9
  Top Layer w4: R269.2@7941.58,5838.92 cw(c7925.68,5823.01) 7948.17,5823.01 cw(c7970.67,5823.01) R269.2@7954.76,5838.92 ; R269.2@7941.58,5853.08 ccw(c7925.68,5868.99) 7948.17,5868.99 ccw(c7970.67,5868.99) R269.2@7954.76,5853.08 ; R281.2@7941.58,5889.25 cw(c7925.68,5873.34) 7948.17,5873.34 cw(c7970.67,5873.34) R281.2@7954.76,5889.25 ; R269.2@7944.41,5841.75 cw(c7935.33,5832.67) 7948.17,5832.67 cw(c7961.01,5832.67) R269.2@7951.93,5841.75 ; R269.2@7944.41,5850.25 ccw(c7935.33,5859.33) 7948.17,5859.33 ccw(c7961.01,5859.33) R269.2@7951.93,5850.25 ; R281.2@7944.41,5892.08 cw(c7935.33,5883) 7948.17,5883 cw(c7961.01,5883) R281.2@7951.93,5892.08 ; R281.2@7948.17,5896.33 R269.2@7948.17,5846 7948.17,5801.83 7953,5797 7953,5388.31 8315.81,5025.5 8315.81,4521.69 8240.02,4445.9 8240.02,4104.11 8164.19,4028.28 8164.19,3742.71 8173.52,3733.37 8406.86,3500.04 v1(8406.86,2475.04) ; v1@8400.14,2481.76 ccw(c8383.92,2497.98) 8406.86,2497.98 ccw(c8429.79,2497.98) v1@8413.57,2481.76 ; v1@8402.97,2478.93 ccw(c8393.58,2488.32) 8406.86,2488.32 ccw(c8420.14,2488.32) v1@8410.75,2478.93
  Top Layer w8: U30.A19@7384.02,1524.51 cw(c7384.02,1510.41) 7393.99,1520.38 cw(c7403.96,1530.35) U30.A19@7389.86,1530.35 ; U30.A19@7384.02,1530.35 v2(7403.7,1510.67) ; v2@7394.7,1510.67 ccw(c7372.97,1510.67) 7388.34,1526.03 ccw(c7403.7,1541.4) v2@7403.7,1519.67
  MidLayer2 w4: v4(7630,1410) 7703.71,1483.71 8190,1483.71 8268,1561.71 8268,1687.56 8318,1737.56 8318,2122 8297,2143 8253.49,2143 8247.86,2148.63 8247.86,2292.86 8260.94,2305.94 8360.94,2305.94 8406.86,2351.86 v1(8406.86,2475.04) ; v4@7630,1415.81 ccw(c7630,1429.84) 7639.92,1419.92 ccw(c7649.84,1410) v4@7635.81,1410 ; v4@7630,1419.81 ccw(c7630,1443.5) 7646.75,1426.75 ccw(c7663.5,1410) v4@7639.81,1410 ; v1@8400.14,2468.32 cw(c8383.92,2452.11) 8406.86,2452.11 cw(c8429.79,2452.11) v1@8413.57,2468.32 ; v1@8402.97,2471.15 cw(c8393.58,2461.76) 8406.86,2461.76 cw(c8420.14,2461.76) v1@8410.75,2471.15
  Bottom Layer w4: v2(7403.7,1510.67) 7474.33,1510.67 7569.2,1415.8 7575,1410 v4(7630,1410) ; v2@7408.65,1505.72 cw(c7420.6,1493.77) 7420.6,1510.67 cw(c7420.6,1527.57) v2@7408.65,1515.62 ; v2@7411.48,1502.89 cw(c7430.26,1484.11) 7430.26,1510.67 cw(c7430.26,1537.23) v2@7411.48,1518.45 ; v4@7623.06,1403.06 ccw(c7606.31,1386.31) 7606.31,1410 ccw(c7606.31,1433.69) v4@7623.06,1416.94 ; v4@7625.89,1405.89 ccw(c7615.97,1395.97) 7615.97,1410 ccw(c7615.97,1424.03) v4@7625.89,1414.11
NetR270_2: R270.2 R282.2 U30.E4 | length 5860.3
  Top Layer w4: R270.2@7709.59,5853.08 ccw(c7693.68,5868.99) 7716.18,5868.99 ccw(c7738.68,5868.99) R270.2@7722.77,5853.08 ; R282.2@7709.59,5889.25 cw(c7693.68,5873.34) 7716.18,5873.34 cw(c7738.68,5873.34) R282.2@7722.77,5889.25 ; R270.2@7712.42,5850.25 ccw(c7703.34,5859.33) 7716.18,5859.33 ccw(c7729.02,5859.33) R270.2@7719.94,5850.25 ; R282.2@7712.42,5892.08 cw(c7703.34,5883) 7716.18,5883 cw(c7729.02,5883) R282.2@7719.94,5892.08 ; R270.2@7716.18,5846 7716.18,5870 ; R282.2@7716.18,5896.33 7716.18,5870 ; 8401.5,3590.23 cw(c8401.5,3566.5) v1@8418.28,3583.28 ; 8402.63,3590.23 ccw(c8402.63,3612.37) v1@8418.28,3596.72 ; 8411.16,3590.23 cw(c8411.16,3576.16) v1@8421.11,3586.11 ; 8412.28,3590.23 ccw(c8412.28,3602.72) v1@8421.11,3593.89 ; v1@8423.52,3591.71 v1@8425,3590.23 ; v1(8425,3590) v1@8425,3590.23 ; 7716.18,5870 7920,5870 7925,5875 7925,5915 7930,5920 7965,5920 7975,5910 7975,5825 7961,5811 7961,5391.63 8323.81,5028.82 8323.81,4518.37 8248.02,4442.59 8248.02,4100.8 8172.19,4024.96 8172.19,3746.02 8327.98,3590.23 v1@8425,3590.23
  Top Layer w8: U30.E4@7226.54,2120.91 v2(7246.22,2140.59) ; U30.E4@7226.54,2126.75 ccw(c7226.54,2140.85) 7236.51,2130.88 ccw(c7246.48,2120.91) U30.E4@7232.38,2120.91 ; v2@7237.22,2140.59 cw(c7215.49,2140.59) 7230.86,2125.23 cw(c7246.22,2109.86) v2@7246.22,2131.59
  MidLayer2 w4: v2@7246.22,2129.59 cw(c7246.22,2103.03) 7265,2121.81 ; v2@7246.22,2133.59 cw(c7246.22,2116.69) 7258.17,2128.64 cw(c7270.12,2140.59) v2@7253.22,2140.59 ; v2(7246.22,2140.59) 7265.44,2121.37 7415.19,2121.37 7566.19,2272.37 7566.19,2415.37 7575.86,2425.04 7673.52,2425.04 7723.52,2475.04 7723.52,3400.04 7781.86,3458.37 8293.37,3458.37 v1(8425,3590) 8425,3590.23 8423.52,3591.71 v1@8423.41,3591.59 ; v2@7257.22,2140.59 ccw(c7283.77,2140.59) 7265,2121.81 ; v1@8415.5,3590 cw(c8392.56,3590) 8408.78,3573.78 cw(c8425,3557.56) v1@8425,3580.5 ; v1@8419.5,3590 cw(c8406.22,3590) 8415.61,3580.61 cw(c8425,3571.22) v1@8425,3584.5
NetR272_1: R272.1 U61.120 | length 150.4
  Top Layer w4: R272.1@5445,2461.33 5461.62,2444.71 5487.11,2444.71 5491.86,2449.46 U61.120@5516.83,2449.46 ; R272.1@5445.49,2452.01 cw(c5445.49,2430.7) 5460.56,2445.77 ; R272.1@5445.49,2456.01 cw(c5445.49,2444.36) R272.1@5453.73,2452.6 ; R272.1@5450.81,2461.24 ccw(c5464.1,2461.02) R272.1@5454.7,2451.63 ; R272.1@5454.81,2461.18 ccw(c5477.23,2460.81) 5461.37,2444.95 ; U61.120@5500.81,2446.63 ccw(c5493.98,2439.8) 5493.98,2449.46 ccw(c5493.98,2459.11) U61.120@5500.81,2452.28
NetR273_1: R273.1 U61.119 | length 534.6
  Top Layer w4: v1(5401.86,2593.71) 5401.97,2593.82 R273.1@5445,2593.82 ; v1@5405.75,2589.82 cw(c5415.4,2580.16) 5415.4,2593.82 ; v1@5405.75,2597.6 ccw(c5414.87,2606.72) 5414.87,2593.82 ; v1@5408.57,2586.99 cw(c5425.06,2570.5) 5425.06,2593.82 ; v1@5408.57,2600.43 ccw(c5424.52,2616.37) 5424.52,2593.82 ; R273.1@5437.92,2587.23 ccw(c5422.01,2571.32) 5422.01,2593.82 ccw(c5422.01,2616.32) R273.1@5437.92,2600.41 ; R273.1@5440.75,2590.06 ccw(c5431.67,2580.98) 5431.67,2593.82 ccw(c5431.67,2606.66) R273.1@5440.75,2597.58 ; v1(5480.19,2466.71) 5482.62,2469.14 U61.119@5516.83,2469.14 ; v1@5484.08,2462.82 cw(c5499.34,2447.56) U61.119@5499.34,2469.14 ; v1@5486.91,2459.99 cw(c5509,2437.9) U61.119@5509,2469.14 ; v1@5486.91,2473.43 ccw(c5497.25,2483.77) 5497.25,2469.14 ; U61.119@5500.81,2466.31 ccw(c5493.98,2459.48) 5493.98,2469.14 ccw(c5493.98,2478.8) U61.119@5500.81,2471.97
  Bottom Layer w4: v1@5395.14,2586.99 cw(c5378.92,2570.77) 5401.86,2570.77 cw(c5424.79,2570.77) v1@5408.57,2586.99 ; v1@5397.97,2589.82 cw(c5388.58,2580.43) 5401.86,2580.43 cw(c5415.14,2580.43) v1@5405.75,2589.82 ; v1(5401.86,2593.71) 5401.86,2545.04 v1(5480.19,2466.71) ; v1@5470.69,2466.71 ccw(c5447.76,2466.71) 5463.97,2482.93 ccw(c5480.19,2499.14) v1@5480.19,2476.21 ; v1@5474.69,2466.71 ccw(c5461.41,2466.71) 5470.8,2476.1 ccw(c5480.19,2485.49) v1@5480.19,2472.21
NetR274_1: R274.1 U62.5 | length 185.5
  Bottom Layer w4: R274.1@5225,956.18 5248.52,956.18 5269.71,935 ; R274.1@5229.25,952.42 cw(c5238.33,943.34) 5238.33,956.18 cw(c5238.33,969.02) R274.1@5229.25,959.94 ; R274.1@5232.08,949.59 cw(c5247.99,933.68) 5247.99,956.18 cw(c5247.99,978.68) R274.1@5232.08,962.77 ; U62.5@5282.08,928.42 ccw(c5269.71,920.07) 5269.71,935 ; U62.5@5282.08,941.58 cw(c5269.71,949.92) 5269.71,935 ; U62.5@5285.4,930.65 ccw(c5277.23,925.14) 5277.23,935 ccw(c5277.23,944.86) U62.5@5285.4,939.35 ; U62.5@5297.76,935 5269.71,935
NetR275_1: R275.1 U63.5 | length 184.2
  Bottom Layer w4: R275.1@5475,913.82 5498.82,913.82 5520,935 ; R275.1@5479.25,910.06 cw(c5488.33,900.98) 5488.33,913.82 cw(c5488.33,926.66) R275.1@5479.25,917.58 ; R275.1@5482.08,907.23 cw(c5497.99,891.32) 5497.99,913.82 cw(c5497.99,936.32) R275.1@5482.08,920.41 ; U63.5@5532.01,928.53 ccw(c5520,920.63) 5520,935 ; U63.5@5532.01,941.47 cw(c5520,949.37) 5520,935 ; U63.5@5535.35,930.72 ccw(c5527.42,925.51) 5527.42,935 ccw(c5527.42,944.49) U63.5@5535.35,939.28 ; U63.5@5547.76,935 5520,935
NetR276_1: R276.1 U64.5 | length 185.5
  Bottom Layer w4: R276.1@5725,956.18 5748.52,956.18 5769.71,935 ; R276.1@5729.25,952.42 cw(c5738.33,943.34) 5738.33,956.18 cw(c5738.33,969.02) R276.1@5729.25,959.94 ; R276.1@5732.08,949.59 cw(c5747.99,933.68) 5747.99,956.18 cw(c5747.99,978.68) R276.1@5732.08,962.77 ; U64.5@5782.08,928.42 ccw(c5769.71,920.07) 5769.71,935 ; U64.5@5782.08,941.58 cw(c5769.71,949.92) 5769.71,935 ; U64.5@5785.4,930.65 ccw(c5777.23,925.14) 5777.23,935 ccw(c5777.23,944.86) U64.5@5785.4,939.35 ; U64.5@5797.76,935 5769.71,935
NetTP11_1: TP11.1 U27.2 Y3.1 | length 881.1
  Top Layer w4: 3544.51,4139.85 ccw(c3572.77,4168.12) TP11.1@3575,4128.2 ; 3544.51,4139.85 cw(c3516.24,4111.58) TP11.1@3556.15,4109.35 ; TP11.1@3548.16,4109.8 ccw(c3492.29,4112.92) 3531.86,4152.5 ; TP11.1@3552.16,4109.57 ccw(c3504.26,4112.25) 3538.18,4146.17 ccw(c3572.1,4180.09) TP11.1@3574.78,4132.2 ; TP11.1@3560.15,4109.13 ccw(c3528.22,4110.91) 3550.83,4133.53 ccw(c3573.44,4156.14) TP11.1@3575.23,4124.21 ; U27.2@3562.76,4357.72 ccw(c3554.42,4349.38) 3554.42,4361.18 ccw(c3554.42,4372.99) U27.2@3562.76,4364.64 ; TP11.1@3574.56,4136.19 cw(c3571.43,4192.07) 3531.86,4152.5 ; TP11.1@3576.12,4108.23 3531.86,4152.5 ; Y3.1@3605.78,4462.24 cw(c3589.03,4445.49) 3612.72,4445.49 cw(c3636.4,4445.49) Y3.1@3619.65,4462.24 ; Y3.1@3608.61,4465.06 cw(c3598.69,4455.14) 3612.72,4455.14 cw(c3626.75,4455.14) Y3.1@3616.83,4465.06 ; Y3.1@3612.72,4480.98 3612.72,4442.28 3632.26,4422.74 3632.26,4377.26 3616.18,4361.18 U27.2@3592.8,4361.18 3541.86,4361.18 3531.86,4351.18 3531.86,4152.5 ; U27.2@3620.26,4361.18 cw(c3630.11,4361.18) 3623.14,4368.14 ; U27.2@3624.26,4361.18 cw(c3643.76,4361.18) 3629.97,4374.97
NetU3_9: U3.9 U3.10 | length 187.9
  Bottom Layer w4: U3.9@4076.5,1072.05 4109.02,1072.05 4109.02,1097.64 U3.10@4076.5,1097.64 ; U3.9@4100.15,1074.88 ccw(c4078.72,1096.31) 4109.02,1096.31 ; U3.10@4100.15,1094.81 cw(c4078.72,1073.38) 4109.02,1073.38 ; U3.9@4102.98,1072.05 ccw(c4088.38,1086.65) 4109.02,1086.65 ; U3.10@4102.98,1097.64 cw(c4088.38,1083.04) 4109.02,1083.04 ; U3.9@4105.8,1069.22 ccw(c4098.03,1076.99) 4109.02,1076.99 ; U3.10@4105.8,1100.47 cw(c4098.03,1092.69) 4109.02,1092.69
NetU27_1: U27.1 Y3.4 | length 216
  Top Layer w4: Y3.4@3577.28,4459.36 cw(c3577.28,4442.36) 3589.3,4454.38 ; Y3.4@3577.28,4480.98 3577.28,4466.4 3620,4423.69 3620,4395 ; Y3.4@3583.09,4469.17 ccw(c3603.81,4469.17) 3589.16,4454.52 ; Y3.4@3587.09,4469.17 ccw(c3617.47,4469.17) 3595.99,4447.7 ; U27.1@3592.8,4386.77 3611.77,4386.77 3620,4395 ; U27.1@3615.91,4390.23 ccw(c3606.04,4400.1) 3620,4400.1 ; U27.1@3617.52,4391.3 ccw(c3616,4395) 3620,4395 ; 3620,4397.06 ccw(c3629.65,4397.06) U27.1@3622.83,4390.23 ; U27.1@3622.19,4390.76 cw(c3625.19,4395) 3620,4395
ONE_WIRE_DB_PB: EXTHDR1.67 R283.2 U8.R2 | length 7046.1
  Top Layer w4: R283.2@1055.38,3150.19 cw(c1055.38,3126.5) 1072.13,3143.25 ; R283.2@1055.38,3154.19 cw(c1055.38,3140.16) R283.2@1065.3,3150.08 ; R283.2@1055.38,3160 1091.95,3123.43 EXTHDR1.67@1091.95,3071.85 1091.95,3075.04 1090.19,3075.04 v1(1090.19,3001.04) ; R283.2@1060.7,3159.5 ccw(c1072.35,3159.5) R283.2@1064.11,3151.27 ; R283.2@1064.7,3159.5 ccw(c1086.01,3159.5) 1070.94,3144.44 ; v1@1083.47,3007.76 ccw(c1067.26,3023.98) 1090.19,3023.98 ccw(c1113.13,3023.98) v1@1096.91,3007.76 ; EXTHDR1.67@1086.29,3021.07 cw(c1076.89,3011.67) v1@1090.19,3011.67 ; v1@1086.3,3004.93 ccw(c1076.91,3014.32) 1090.19,3014.32 ccw(c1103.47,3014.32) v1@1094.08,3004.93 ; v1@1090.19,3003.16 cw(c1115.52,3003.16) EXTHDR1.67@1097.61,3021.07 ; 1090.19,3012.82 cw(c1105.86,3012.82) EXTHDR1.67@1094.78,3023.9 ; 4851.26,4115.44 4854.96,4115.44 ; 4855.26,4115.44 4854.96,4115.44 ; U8.R2@4929.9,4130.94 cw(c4912.17,4130.94) 4924.71,4118.41 ; U8.R2@4937.24,4123.6 ccw(c4937.24,4105.88) 4924.71,4118.41 ; 4599.58,4136.32 cw(c4608.97,4145.71) 4595.69,4145.71 ccw(c4608.97,4145.71) 4599.58,4136.32 ; 4599.58,4136.32 ccw(c4590.19,4126.93) 4590.19,4140.21 cw(c4590.19,4126.93) 4599.58,4136.32 ; 4606.41,4129.49 cw(c4622.63,4145.71) 4599.69,4145.71 ccw(c4622.63,4145.71) 4606.41,4129.49 ; 4606.41,4129.49 ccw(c4590.19,4113.27) 4590.19,4136.21 cw(c4590.19,4113.27) 4606.41,4129.49 ; 4611.69,4124.21 4693.42,4124.21 4705.25,4112.37 4776.98,4112.37 4780.04,4115.44 4854.96,4115.44 ; 4611.69,4124.21 v1(4590.19,4145.71) 4611.69,4124.21 ; 4854.96,4115.44 4860,4115.44 4870,4115.44 4917.53,4115.44 ccw(c4917.53,4125.59) 4924.71,4118.41
  MidLayer1 w4: v1@1083.47,3007.76 ccw(c1067.26,3023.98) 1090.19,3023.98 ccw(c1113.13,3023.98) v1@1096.91,3007.76 ; v1@1086.3,3004.93 ccw(c1076.91,3014.32) 1090.19,3014.32 ccw(c1103.47,3014.32) v1@1094.08,3004.93 ; v1(1090.19,3001.04) 1090.19,3183.37 1098.52,3191.71 1606.86,3191.71 1656.86,3141.71 1745.19,3141.71 1795.19,3191.71 2158.29,3191.71 2178,3172 2178,2996.48 2131.52,2950 2131.52,2811.69 2178.09,2765.13 2826.69,2765.13 3220,3158.44 3220,4045 3233.04,4058.04 3303.04,4058.04 3323.52,4078.52 3323.52,4523.52 3342.04,4542.04 4087.96,4542.04 4120,4510 4120,4386.9 v1(4140.19,4366.71) ; v1@4130.69,4366.71 ccw(c4107.76,4366.71) 4123.97,4382.93 ccw(c4140.19,4399.14) v1@4140.19,4376.21 ; v1@4134.69,4366.71 ccw(c4121.41,4366.71) 4130.8,4376.1 ccw(c4140.19,4385.49) v1@4140.19,4372.21
  MidLayer2 w4: v1@4140.19,4357.21 cw(c4140.19,4334.27) 4156.41,4350.49 cw(c4172.63,4366.71) v1@4149.69,4366.71 ; v1@4140.19,4361.21 cw(c4140.19,4347.93) 4149.58,4357.32 cw(c4158.97,4366.71) v1@4145.69,4366.71 ; v1(4140.19,4366.71) 4181.86,4325.04 4266.86,4325.04 ; 4245,4325 4266.9,4325 ; v1@4580.69,4145.71 ccw(c4557.76,4145.71) 4573.97,4161.93 ccw(c4590.19,4178.14) v1@4590.19,4155.21 ; v1@4584.69,4145.71 ccw(c4571.41,4145.71) 4580.8,4155.1 ccw(c4590.19,4164.49) v1@4590.19,4151.21 ; v1(4590.19,4145.71) 4427.86,4308.04 4295.54,4308.04 4278.59,4325 4266.9,4325 ; 4266.86,4325.04 4266.9,4325
PB_AIN.L: C6.2 EXTHDR1.33 R22.1 | length 5282.5
  Top Layer w4: v1(1625,2940) 1627.39,2942.39 EXTHDR1.33@1627.39,3071.85
  MidLayer1 w4: v1(-9.81,2658.37) -32.5,2635.68 -32.5,2421.4 v1(20.19,2368.71) ; v1(765,2575) 708.02,2518.02 708.02,2208.02 627,2127 627,1076.18 711.48,991.71 v1(1081.86,991.71)
  Bottom Layer w4: R22.1@-53.82,2640 -28.18,2640 v1(-9.81,2658.37) ; v1(20.19,2368.71) 43.37,2345.52 725.52,2345.52 740,2360 740,2495 765.19,2520.19 v1@765.19,2574.04 ; v1@765.19,2575 765.19,2592 765.19,2670 756.02,2679.17 756.02,2772.35 611.52,2916.85 611.52,2993.82 621.52,3003.81 778.09,3003.81 877.81,2904.09 1210.91,2904.09 1238.19,2931.37 1238.19,2961.22 1254.01,2977.04 1276.37,2977.04 1292.19,2961.22 1292.19,2928.12 1308.88,2911.43 1492.97,2911.43 1509.03,2895.37 1580.37,2895.37 v1(1625,2940) ; v1(1081.86,991.71) 1148.29,991.71 1154.33,985.67 C6.2@1154.33,950
PB_AIN.MIC: EXTHDR1.37
PB_AIN.R: C5.2 EXTHDR1.35 R26.1 | length 4908.7
  Top Layer w4: v1@1593.57,3000 v1(1590,3000) 1595.89,3005.89 EXTHDR1.35@1595.89,3071.85
  MidLayer1 w4: v1(-18.14,2901.71) -18.14,2813.14 50,2745 270.04,2745 290,2725.04 v1(690.19,2725.04) 645,2679.85 645,2581.02 681.02,2545 681.02,2219.21 600,2138.18 600,1065 735,930 1295.15,930 v1(1356.86,991.71)
  Bottom Layer w4: R26.1@-53.82,2891.25 -28.6,2891.25 v1(-18.14,2901.71) ; v1(690.19,2725.04) 690.19,2800 584.52,2905.67 584.52,3005 610.33,3030.81 1559.19,3030.81 v1(1590,3000) ; C5.2@1354.32,950 v1@1354.32,989.17
PB_AOUT.L: C9.2 EXTHDR1.31 | length 2955.7
  Top Layer w4: EXTHDR1.31@1658.88,3071.85 1658.88,3189.4 1660,3190.52 v1(1660,3270) v1@1664.48,3265.52
  MidLayer2 w4: v1@-251.48,3675.04 -255,3671.52 v1(-255,3670) -30,3670 -1.27,3698.73 -1.27,3838.73 14.73,3854.73 855,3854.73 ; 790,3854.73 855,3854.73 ; v1(1660,3270) 1660.25,3270 1660.31,3270.06 1660.31,3270.59 1629.62,3301.28 1629.62,3820.5 1595.38,3854.73 855,3854.73
  Bottom Layer w4: C9.2@-279.33,3685 -261.44,3685 ; C9.2@-271.06,3679.72 cw(c-261.44,3673.59) -261.44,3685 ; C9.2@-271.06,3690.28 ccw(c-261.44,3696.41) -261.44,3685 ; v1(-255,3670) -255,3678.56 -261.43,3685
PB_AOUT.R: C16.2 EXTHDR1.29 | length 3796.2
  Top Layer w4: EXTHDR1.29@1690.38,3071.85 1690.38,3155.19 v1(1715.19,3180)
  MidLayer1 w4: v1(1149.86,4635.71) 1345.56,4440 1695,4440 1723.52,4411.48 1723.52,3188.33 v1(1715.19,3180)
  Bottom Layer w4: C16.2@-179.33,4184.09 -100,4184.09 -75,4209.09 -75,4320.04 -89.96,4335 -120,4335 -135,4350 -135,4390 -120,4405 50,4405 115.5,4470.5 695.5,4470.5 719.06,4494.06 794.06,4494.06 835,4535 835,4610 870,4645 975,4645 984.29,4635.71 v1(1149.86,4635.71)
PB_SPI.DIN: EXTHDR1.55 U30.Y14 | length 7038.9
  Top Layer w4: EXTHDR1.55@1275.27,3122.62 ccw(c1261.61,3136.28) 1280.93,3136.28 ccw(c1300.24,3136.28) EXTHDR1.55@1286.58,3122.62 ; EXTHDR1.55@1280.93,3071.85 1280.93,3149.11 1356.86,3225.04 1484.84,3225.04 1593.17,3333.37 2270.54,3333.37 2775,2828.92 2775,2430 v1(2750,2405) ; v1@2750,2410.5 ccw(c2750,2423.78) 2759.39,2414.39 ccw(c2768.78,2405) v1@2755.5,2405 ; v1@2750,2414.5 ccw(c2750,2437.43) 2766.22,2421.22 ccw(c2782.43,2405) v1@2759.5,2405
  Top Layer w8: v2(6616.3,1707.52) U30.Y14@6635.98,1727.2 ; v2@6616.3,1716.52 ccw(c6616.3,1738.25) 6631.66,1722.88 ccw(c6647.03,1707.52) v2@6625.3,1707.52 ; U30.Y14@6630.14,1727.2 cw(c6616.04,1727.2) 6626.01,1717.23 cw(c6635.98,1707.26) U30.Y14@6635.98,1721.36
  MidLayer2 w4: v1(6107.52,1724.37) 6133.19,1750.04 6234.84,1750.04 6251.5,1766.71 6490.19,1766.71 6540.52,1716.37 6585.67,1716.37 6594.52,1707.52 ; v1@6107.52,1729.87 ccw(c6107.52,1743.15) 6116.91,1733.76 ccw(c6126.3,1724.37) v1@6113.02,1724.37 ; v1@6107.52,1733.87 ccw(c6107.52,1756.81) 6123.74,1740.59 ccw(c6139.96,1724.37) v1@6117.02,1724.37 ; v2@6607.44,1700.99 ccw(c6594.53,1691.47) 6594.53,1707.52 ; v2@6607.45,1714.05 cw(c6594.52,1723.57) 6594.52,1707.52 ; v2@6610.66,1703.37 ccw(c6602.44,1697.31) 6602.44,1707.52 ccw(c6602.44,1717.73) v2@6610.66,1711.67 ; v2(6616.3,1707.52) 6594.52,1707.52
  Bottom Layer w4: v1@2750,2395.5 cw(c2750,2372.56) 2766.22,2388.78 cw(c2782.43,2405) v1@2759.5,2405 ; v1@2750,2399.5 cw(c2750,2386.22) 2759.39,2395.61 cw(c2768.78,2405) v1@2755.5,2405 ; v1(2750,2405) 2770,2385 2980,2385 3049.5,2315.5 3278.71,2315.5 3307.71,2286.5 3372.19,2286.5 3375.69,2283 3662.84,2283 3662.96,2282.87 4354.38,2282.87 4373.52,2263.73 4373.52,2000 4392.71,1980.81 4942.75,1980.81 4965.19,1958.37 5194.86,1958.37 5319.86,1833.37 5876.88,1833.37 6001.88,1708.37 6091.52,1708.37 ; v1@6098.02,1724.28 cw(c6075.83,1724.07) 6091.53,1708.38 ; v1@6102.02,1724.32 cw(c6089.18,1724.2) 6098.26,1715.11 cw(c6107.35,1706.03) v1@6107.47,1718.88 ; v1@6107.43,1714.88 ccw(c6107.22,1692.68) 6091.53,1708.38 ; v1(6107.52,1724.37) 6091.52,1708.37
PB_SPI.DOUT: EXTHDR1.53 U30.V14 | length 7393
  Top Layer w4: v1(1290.87,3000.72) 1290.19,3000.04 1304.42,3000.04 1312.42,3008.04 ; EXTHDR1.53@1306.9,3020.94 cw(c1294.6,3008.04) 1312.42,3008.04 ; EXTHDR1.53@1312.42,3071.85 1312.42,3008.04 ; EXTHDR1.53@1317.95,3020.94 ccw(c1330.25,3008.04) 1312.42,3008.04
  Top Layer w8: v2(6695.04,1707.52) U30.V14@6714.72,1727.2 ; v2@6695.04,1716.52 ccw(c6695.04,1738.25) 6710.4,1722.88 ccw(c6725.77,1707.52) v2@6704.04,1707.52 ; U30.V14@6708.88,1727.2 cw(c6694.78,1727.2) 6704.75,1717.23 cw(c6714.72,1707.26) U30.V14@6714.72,1721.36
  MidLayer1 w4: v1(1290.87,3000.72) 1315.19,3025.04 1460,3025.04 1484.96,3050 1703.31,3050 1719,3034.31 1719,2821 1735,2805 ; v1@1290.87,3006.22 ccw(c1290.87,3019.5) 1300.26,3010.11 ccw(c1309.65,3000.72) v1@1296.37,3000.72 ; v1@1290.87,3010.22 ccw(c1290.87,3033.16) 1307.09,3016.94 ccw(c1323.31,3000.72) v1@1300.37,3000.72 ; 1735.12,2805.12 2031.86,2508.37 v1(2031.86,2255) ; v1@2025.14,2261.72 ccw(c2008.92,2277.93) 2031.86,2277.93 ccw(c2054.79,2277.93) v1@2038.57,2261.72 ; v1@2027.97,2258.89 ccw(c2018.58,2268.28) 2031.86,2268.28 ccw(c2045.14,2268.28) v1@2035.75,2258.89
  Bottom Layer w4: v1(2031.86,2255) 2064.88,2288.02 2216.98,2288.02 2222.9,2282.1 2252.1,2282.1 2265,2295 2742.62,2295 2746.12,2291.5 3268.77,2291.5 3297.77,2262.5 3362.25,2262.5 3365.87,2258.87 4285,2258.87 4357.52,2186.35 4357.52,1984.12 4329.8,1956.4 4329.8,1925.35 ; v1@2031.86,2260.5 ccw(c2031.86,2273.78) 2041.25,2264.39 ccw(c2050.64,2255) v1@2037.36,2255 ; v1@2031.86,2264.5 ccw(c2031.86,2287.43) 2048.07,2271.22 ccw(c2064.29,2255) v1@2041.36,2255 ; 4265,1641.71 4565.19,1641.71 4574.19,1632.71 4969.69,1632.71 5039.98,1703 5667,1703 5686.63,1683.37 5858.19,1683.37 5958.19,1583.37 6156.86,1583.37 6173.52,1600.04 6256.86,1600.04 6290.19,1633.37 6445,1633.37 6453.33,1641.71 6598.52,1641.71 6604.86,1648.04 6625.19,1648.04 6635.52,1658.37 6635.52,1675.04 6647.67,1687.19 6674.71,1687.19 v2(6695.04,1707.52) ; 4265,1642.2 4248.86,1658.35 4248.86,1728.86 4270,1750 4310,1750 4325,1765 4325,1887.5 4323.02,1889.48 4323.02,1910.6 4330,1917.58 4330,1925.35 ; v2@6684.04,1707.52 cw(c6657.48,1707.52) 6676.26,1688.74 cw(c6695.04,1669.96) v2@6695.04,1696.52 ; v2@6688.04,1707.52 cw(c6671.14,1707.52) 6683.09,1695.57 cw(c6695.04,1683.62) v2@6695.04,1700.52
